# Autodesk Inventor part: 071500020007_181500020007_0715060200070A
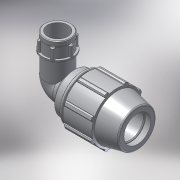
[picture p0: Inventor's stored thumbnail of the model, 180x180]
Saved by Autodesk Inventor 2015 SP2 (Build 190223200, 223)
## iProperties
Created: 2017-02
Part Number: 071500020007_181500020007_0715060200070A
Material: PVC-Piping
Description: PLASSON 90° ELBOW FEMALE ADAPTOR 20-3/4"
Document SubType Name: Modeling
Designer: KIM
Mass: 92.6774 g
Surface Area: 199.44 cm^2
Volume: 66.1981 cm^3
Density: 1.4 g/cm^3
Appearance: Smooth - White
Author: KIM
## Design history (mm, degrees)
derived "07150.ipt"
feature "Solid1::07150.ipt"
tag "TaggingFeature1"
body "Solid1"
other parameters: "d4" = 6.5, "d5" = 19.5, "d7" = 48, "d9" = 11.14286, "d11" = 2.6, "d13" = 120 deg, "d15" = 12 deg, "d16" = 41.76, "d18" = 1, "d19" = 35 deg, "d20" = 17.5 deg, "d21" = 44.64, "d23" = 0, "d25" = 360 deg, "d27" = 0.96, "d33" = 0.4, "d42" = 28.86, "d43" = 1.44, "d46" = 0.6, "d51" = 78, "d68" = 2.6, "d72" = 44, "d73" = 31.3521, "d74" = 19, "d75" = 36.05492, "d76" = 24.117, "d77" = 20.9, "d79" = 9.6468, "d80" = 0.72351, "d83" = 0, "d84" = 0, "d91" = 36, "d93" = 57, "d94" = 24.117, "d95" = 16.8819, "d96" = 7.8, "d97" = 50 deg, "d98" = 21.7053, "d99" = 0.5, "d100" = 0.5, "d101" = 6.33333, "d102" = 31.3521, "d103" = 16.15, "d104" = 0, "d108" = 360 deg, "d110" = 0.94056, "E_" = 48, "A_" = 78, "l_" = 57, "l_2" = 19, "A_1" = 44, "Rp_" = 24.117, "d105" = 4.70281
